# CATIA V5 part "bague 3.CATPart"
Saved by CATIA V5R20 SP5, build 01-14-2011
Part number: bague 3
Bounding box of the stored display mesh (mm): x 0 to 5, y -54.952 to 54.952, z -63.952 to 63.952
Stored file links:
  U:\IAO\Nouveau dossier\bague 3.CATPart
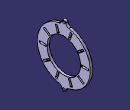
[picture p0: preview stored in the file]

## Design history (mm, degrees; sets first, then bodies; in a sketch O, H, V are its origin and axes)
Body1 (main body)
  Sketch1 on yz-plane, origin (0, 0, 0), H (0, 1, 0), V (0, 0, 1)
    arc A1 centre (0, 0) radius 55 from (-10.3492, 54.0175) to (-10.3492, -54.0175) ccw
    circle A2 centre (0, 0) radius 35
    arc A3 centre (0, 60) radius 4 from (3.9392, 60.6946) to (-3.9392, 60.6946) ccw
    point P1 (0, 60)
    line L1 (-3.9392, 60.6946) -> (-3.9761, 60.4854)
    point P2 (-3.9392, 60.6946)
    line L2 (3.9392, 60.6946) -> (3.9761, 60.4854)
    point P3 (3.9392, 60.6946)
    arc A4 centre (11.8546, 61.8746) radius 8 from (10.3492, 54.0175) to (3.9761, 60.4854) cw
    point P4 (10.3492, 54.0175)
    point P5 (3.9761, 60.4854)
    arc A5 centre (-11.8546, 61.8746) radius 8 from (-10.3492, 54.0175) to (-3.9761, 60.4854) ccw
    point P7 (-10.3492, 54.0175)
    point P8 (-3.9761, 60.4854)
    point P10 (-3.9761, -60.4854)
    point P11 (-10.3492, -54.0175)
    arc A6 centre (-11.8546, -61.8746) radius 8 from (-10.3492, -54.0175) to (-3.9761, -60.4854) cw
    point P13 (-3.9392, -60.6946)
    line L3 (-3.9392, -60.6946) -> (-3.9761, -60.4854)
    point P14 (3.9392, -60.6946)
    arc A7 centre (0, -60) radius 4 from (3.9392, -60.6946) to (-3.9392, -60.6946) cw
    point P16 (3.9761, -60.4854)
    line L4 (3.9392, -60.6946) -> (3.9761, -60.4854)
    point P17 (10.3492, -54.0175)
    arc A8 centre (11.8546, -61.8746) radius 8 from (10.3492, -54.0175) to (3.9761, -60.4854) ccw
    arc A9 centre (0, 0) radius 55 from (10.3492, -54.0175) to (10.3492, 54.0175) ccw
    circle A10 centre (0, 60) radius 2.5
    point P19 (0, 60)
    circle A11 centre (0, -60) radius 2.5
    radius A1 = 55
    radius A2 = 35
    radius A3 = 4
    distance P1 H = 60
    angle L2 V = 10
    radius A4 = 8
    radius A5 = 8
    distance P19 H = 60
    radius A10 = 2.5
    coincidence: P1 V, A1 A9, P19 V
    tangency: L2 A3, L1 A3, A4 A1, A4 L2, A5 A1, A5 L1
    symmetry: L2 L1 V, P8 P10 H, P7 P11 H, A5 A6 H, P2 P13 H, L1 L3 H, P3 P14 H, A3 A7 H, P5 P16 H, L2 L4 H, P4 P17 H, A4 A8 H, A10 A11 H
  Pad1: profile Sketch1, direction (1, 0, 0), length 5
  Sketch2 on start face of Pad1, origin (0, 0, 0), H (0, -1, 0), V (0, 0, 1)
    line L1 (37, 2) -> (51, 2)
    line L2 (51, 2) -> (51, -2)
    line L3 (51, -2) -> (37, -2)
    line L4 (37, -2) -> (37, 2)
    distance L1 H = 2
    distance L4 L2 = 14
    distance L4 V = 37
    horizontal: L1 H, L3 H
    vertical: L2 V, L4 V
    symmetry: L1 L3 H
  Pocket1: profile Sketch2, direction (1, 0, 0), length 5
  CircPattern1: of Pocket1, instances 10, angular step 36 {= 360.0*1 deg/CircPattern1.AngularNumber}, axis from start face of Pad1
